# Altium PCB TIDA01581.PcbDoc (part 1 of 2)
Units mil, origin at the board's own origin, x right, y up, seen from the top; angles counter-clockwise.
Board outline 3050 x 2610 mil, 2 copper layers (Top Layer, Bottom Layer), stack 62 mil thick; 135 components, 67 nets, 345 pads, 231 vias.
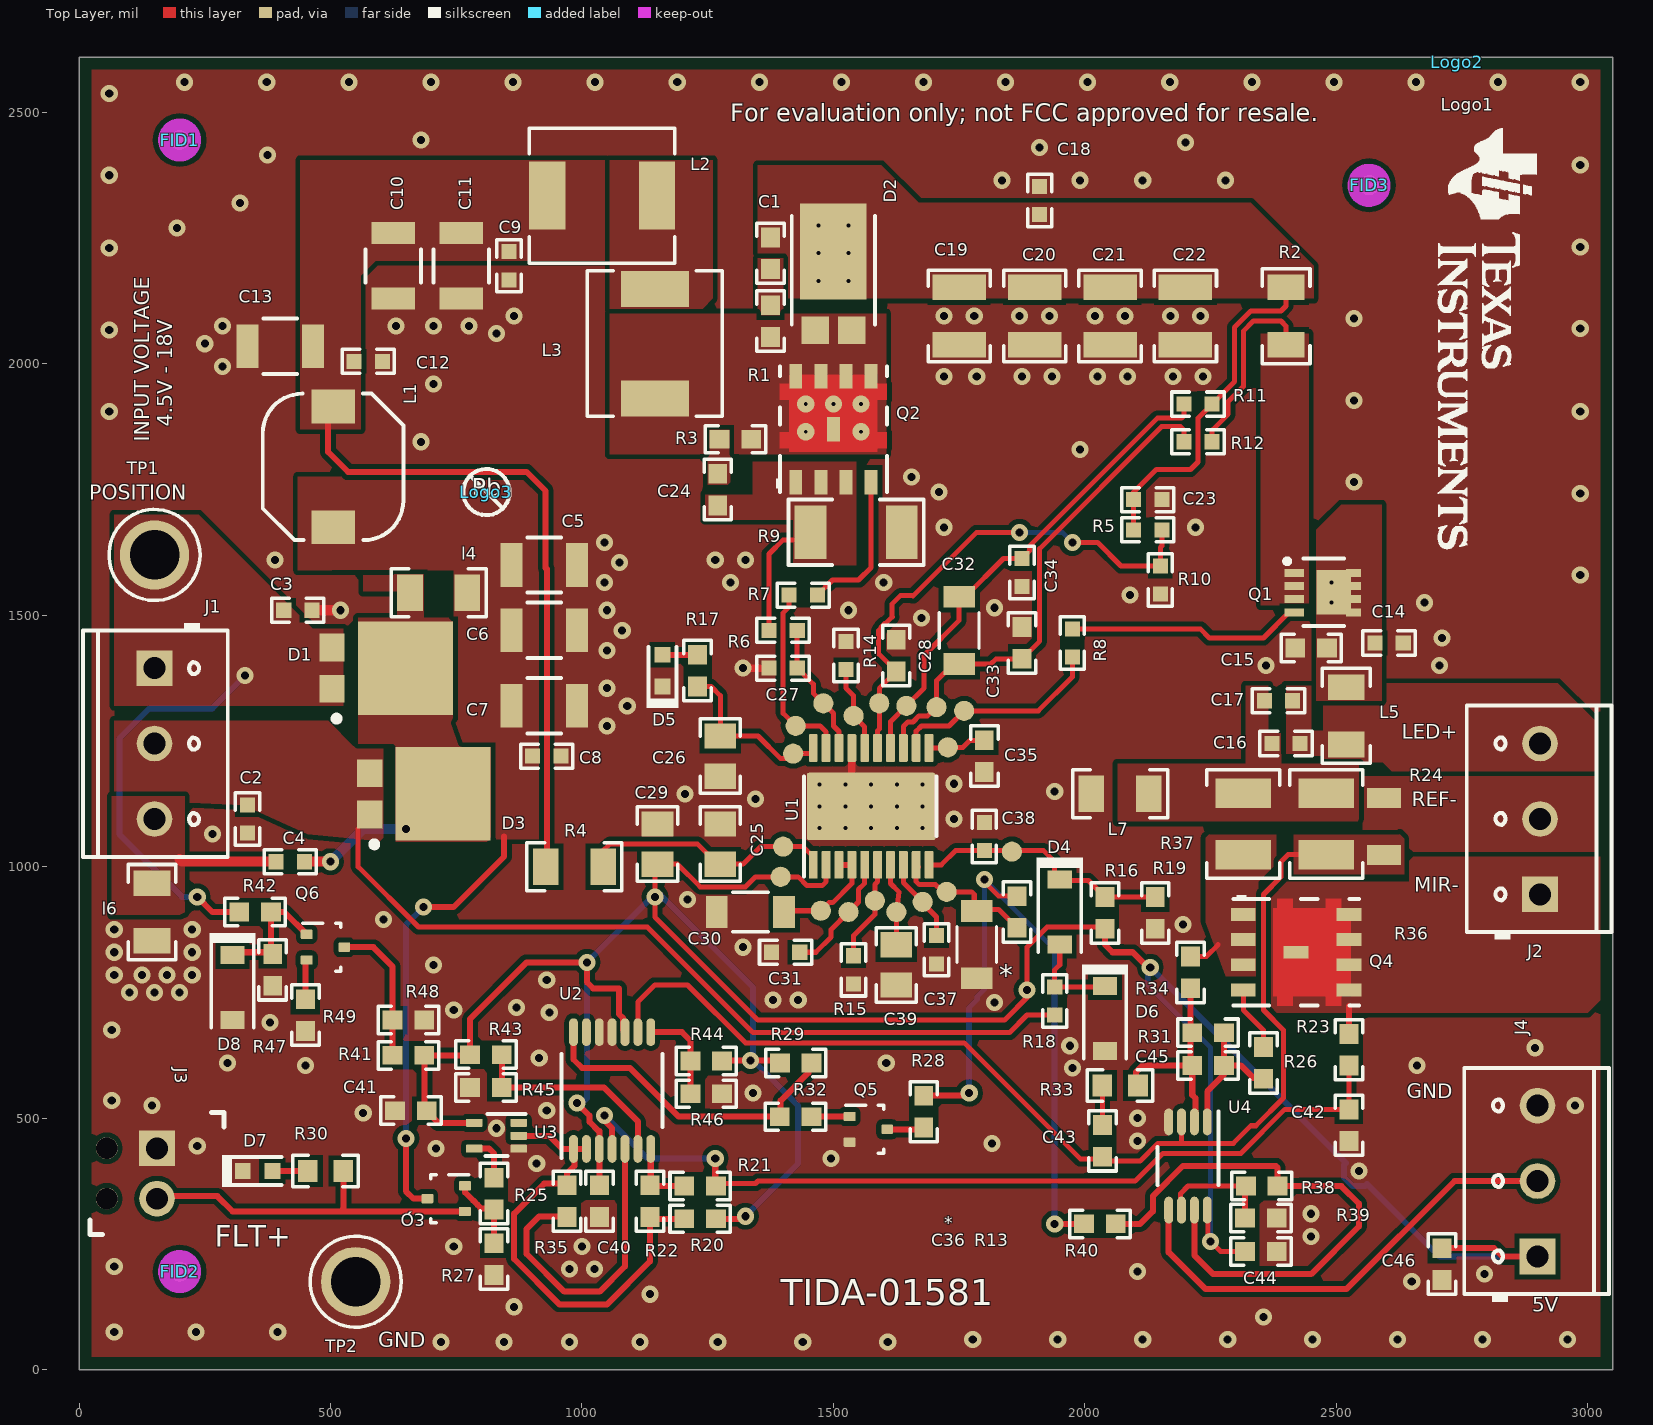
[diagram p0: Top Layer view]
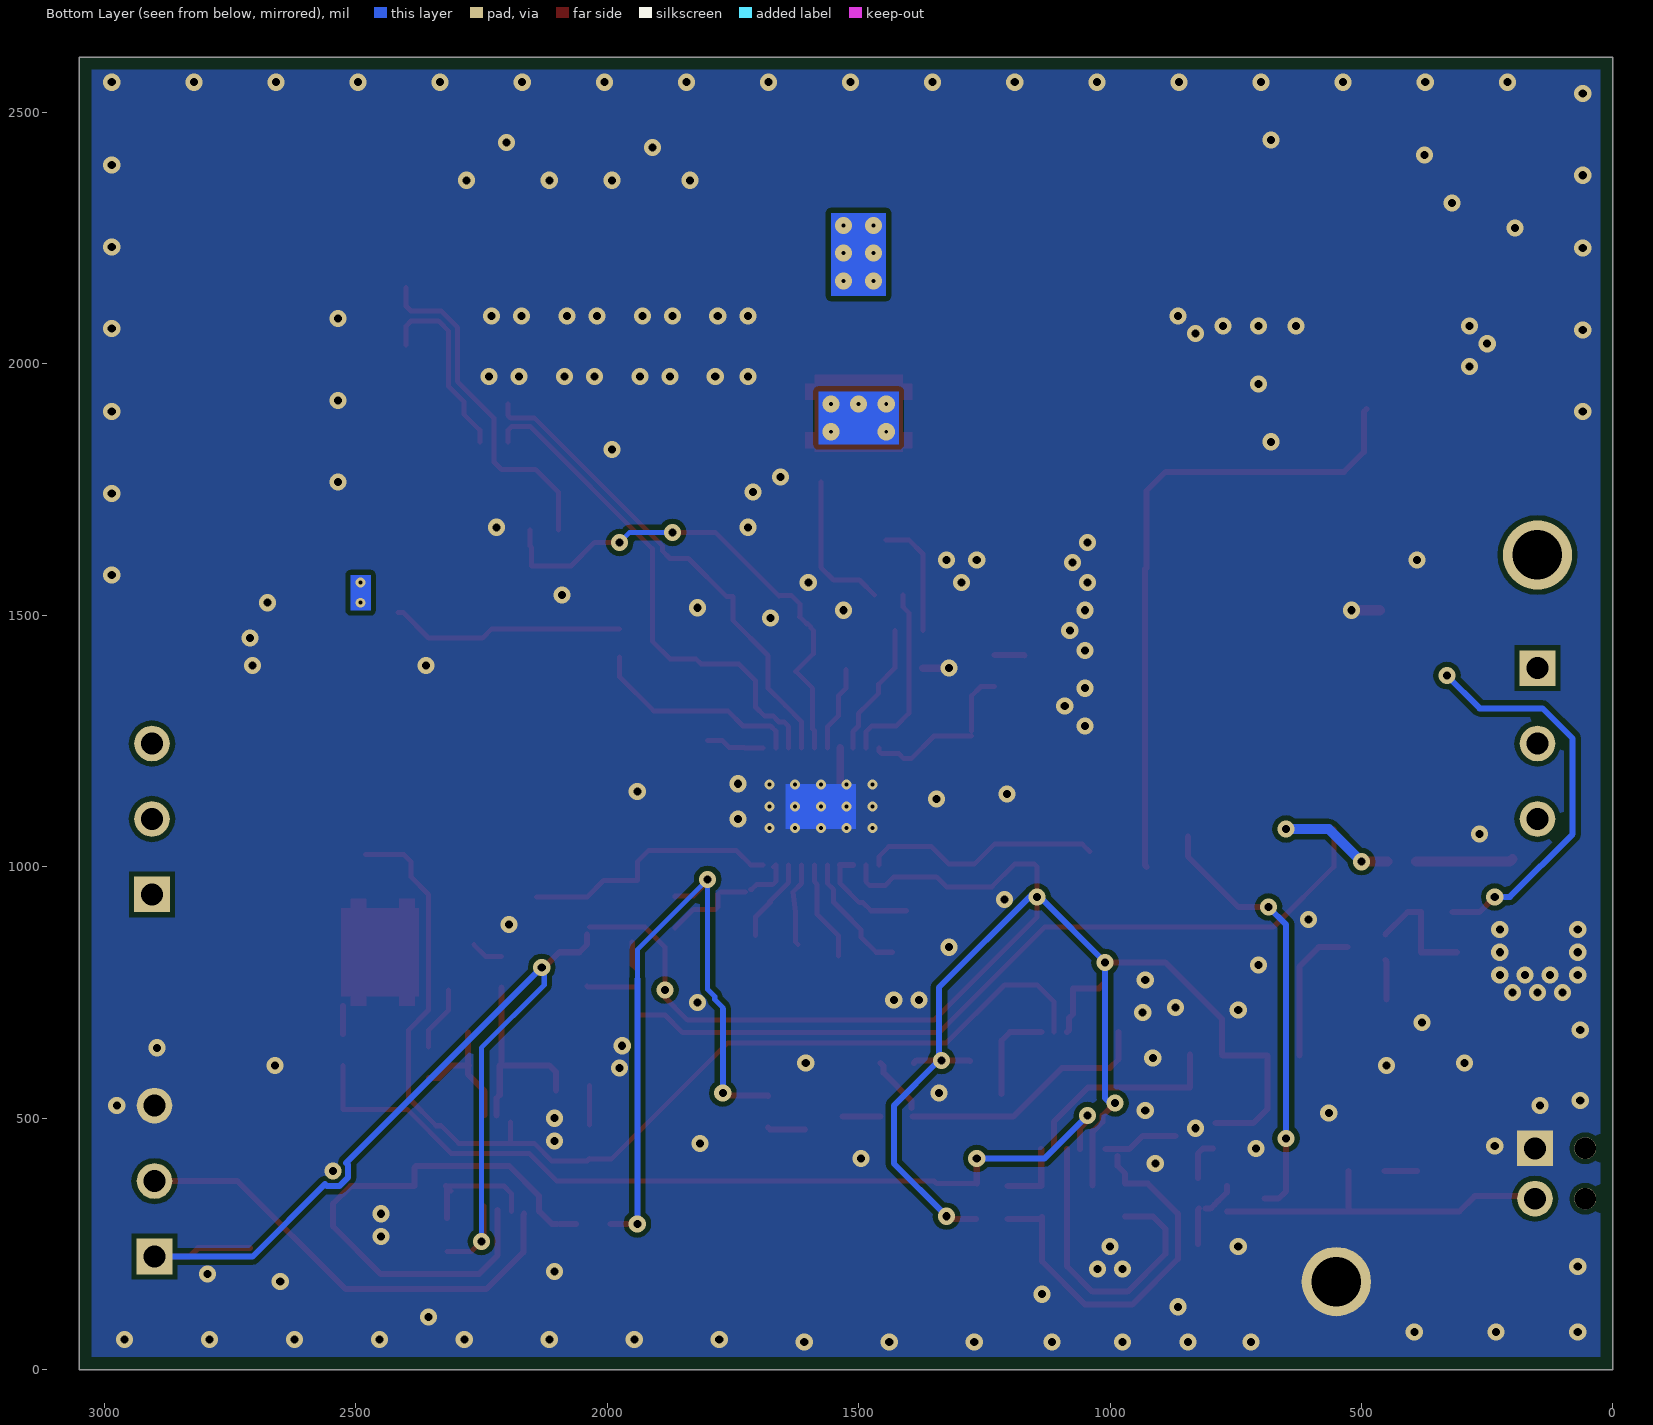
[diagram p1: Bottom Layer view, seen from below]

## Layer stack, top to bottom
Top Solder: solder mask 0.4, Solder Resist, Dk 3.5
Top Layer: signal copper 1.4
Dielectric1: core 59.2, FR-4, Dk 4.8
Bottom Layer: signal copper 1.4
Bottom Solder: solder mask 0.4, Solder Resist, Dk 3.5

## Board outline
0,0 0,2610 3050,2610 3050,0

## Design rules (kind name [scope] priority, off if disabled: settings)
AcuteAngle [All] p1: minimum=4.00000000000000E+0001 checktracksonly=FALSE
AssemblyTestPointUsage [All] p1: valid=2
BoardOutlineClearance BoardOutlineClearance_MountingHoles [OnCopper and InComponentClass('Mounting Holes')] p1: gap=40
BoardOutlineClearance BoardOutlineClearance_Poly [OnCopper and InPoly] p2: gap=25
BoardOutlineClearance [OnCopper and Not InComponentClass('Logo') and not InComponentClass('FiducialMark') and not InRegion(1000,500,4000,800)] p3: gap=25
Clearance Clearance_Keepouts [((IsTrack Or IsArc) And Not InPoly) And IsFree and IsKeepOut vs ((IsTrack Or IsArc) And Not InPoly) And IsFree and IsKeepOut] p1: gap=0
Clearance Clearance_Poly [InPolygon] p2: gap=10
Clearance [All] p3: gap=7
ComponentClearance ComponentClearance_Logo4-R11 [InComponent('LOGO4') vs InComponent('R11')] p1: gap=-1 collisioncheckmode=3 verticalgap=-1 showdistances=FALSE
ComponentClearance ComponentClearance_Logo1-SHJ4 [InComponent('Logo1') vs InComponent('SH-J4')] p2: gap=-1 collisioncheckmode=3 verticalgap=-1 showdistances=FALSE
ComponentClearance ComponentClearance_Logo1-J4 [InComponent('Logo1') vs InComponent('J4')] p3: gap=-1 collisioncheckmode=3 verticalgap=-1 showdistances=FALSE
ComponentClearance ComponentClearance_Shunts [HasFootprint('Wurth_60900213521') vs InComponentClass('Header')] p4: gap=-1 collisioncheckmode=3 verticalgap=-1 showdistances=FALSE
ComponentClearance [All] p5: gap=5 collisioncheckmode=3 verticalgap=5 showdistances=FALSE
DiffPairsRouting [All] p1: maxlimit=100 minlimit=10 mostfreqgap=10 toplayer_minwidth=15 toplayer_maxwidth=15 toplayer_prefwidth=15 bottomlayer_minwidth=15 bottomlayer_maxwidth=15 bottomlayer_prefwidth=15 maxuncoupledlength=1000
FabricationTestPointUsage TestPointUsage [All] p1: valid=2 allowmultiple=FALSE
FabricationTestpoint Testpoint [All] p1: side=3 testpointundercomponent=TRUE minsize=40 maxsize=100 preferedsize=60 minholesize=0 maxholesize=40 preferedholesize=32 testpointgrid=1 allowsidetop=TRUE allowsidebottom=TRUE usegrid=TRUE gridtolerance=0.01
FanoutControl Fanout_LCC [IsLCC] p1: bgadir=Out bgaviamode=Centered fanoutstyle=Auto fanoutdirection=Alternating viagrid=1 // Fanout_LCC (Default Rule)
FanoutControl Fanout_BGA [IsBGA] p2: bgadir=Out bgaviamode=Centered fanoutstyle=Auto fanoutdirection=Alternating viagrid=1 // Fanout_BGA (Default Rule)
FanoutControl Fanout_Default [All] p4: bgadir=Out bgaviamode=Centered fanoutstyle=Auto fanoutdirection=Alternating viagrid=1 // Fanout_Default (Default Rule)
FanoutControl Fanout_Small [(CompPinCount < 5)] p5: bgadir=Out bgaviamode=Centered fanoutstyle=Auto fanoutdirection=OutThenIn viagrid=1 // Fanout_Small (Default Rule)
HoleSize [All] p1: absolutevalues=TRUE maxlimit=251 minlimit=7.87 maxpercent=80.000 minpercent=20.000
MinimumAnnularRing MinimumAnnularRing_ThermalPadVias [IsVia and InAnyComponent] p1: minimumring=5.91
MinimumAnnularRing [All] p2: minimumring=8
MinimumSolderMaskSliver MinimumSolderMaskSliver_Logo [InComponentClass('Logo') vs InComponentClass('Logo')] p1: minsoldermaskwidth=0.7
MinimumSolderMaskSliver [All] p2: minsoldermaskwidth=3.94
PlaneConnect [All] p1: planeconnectstyle=Relief reliefexpansion=10 reliefentries=4 reliefconductorwidth=10 reliefairgap=10
PolygonConnect [All] p1: connectstyle=Direct reliefconductorwidth=10 reliefentries=4 polygonreliefangle="90 Angle" airgapwidth=10
RoutingVias ThermalPadVias [IsVia and InAnyComponent] p1: holewidth=7.87 width=19.68 viastyle="Through Hole" minholewidth=7.87 minwidth=19.68 maxholewidth=12.99 maxwidth=23.62
RoutingVias [All] p2: holewidth=16 width=34 viastyle="Through Hole" minholewidth=7.87 minwidth=26 maxholewidth=40 maxwidth=65
SilkToBoardRegionClearance [Not ((IsComment or IsDesignator) And (Hide <> 'False')) and not InRegion(1000,500,4000,800)] p1:
SilkToSilkClearance SilkToSilkClearance_Pb-FreeLogo [(HasFootprint('Pb-Free_Overlay_Medium') OR HasFootprint('Pb-Free_Overlay_Small')) vs (HasFootprint('Pb-Free_Overlay_Medium') OR HasFootprint('Pb-Free_Overlay_Small'))] p1: silktosilkclearance=0
SilkToSilkClearance [All] p2: silktosilkclearance=3
SilkToSolderMaskClearance SilkToComponentPadClearance [IsPad and InAnycomponent] p1: minsilkscreentomaskgap=4 clearancetoexposedcopper=TRUE
SilkToSolderMaskClearance "Silk to Solder Mask Opening" [All] p2: minsilkscreentomaskgap=4 clearancetoexposedcopper=FALSE
SolderMaskExpansion [All] p1: expansion=1.97
Width [All] p1: maxlimit=100 minlimit=6 preferedwidth=10 checkconnectedcopper=TRUE
15 further rules are at their usual default settings.

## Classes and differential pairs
component class TIDA01581_1: C1 C2 C3 C4 C5 C6 C7 C8 C9 C10 C11 C12 C13 C14 C15 C16 C17 C18 C19 C20 C21 C22 C23 C24 C25 C26 C27 C28 C29 C30 C31 C32 C33 C34 C35 C36 C37 C38 C39 D1 D2 D3 D4 D8 J1 L1 L2 L3 l4 L5 l6 L7 Q1 Q2 R1 R2 R3 R4 R5 R6 R7 R8 R9 R10 R11 R12 R13 R14 R15 R16 R18 R19 R20 TP1 TP2 U1
component class Logo: Logo1
component class TIDA01581_Hardware: FID1 FID2 FID3 Logo1 Logo2 Logo3 ZZ1 ZZ2 ZZ3
component class FiducialMark: FID1 FID2 FID3
component class AssemblyNote: ZZ1 ZZ2 ZZ3
component class TIDA01581_2: C40 C41 C42 C43 C44 C45 C46 D7 D8 J2 J3 J4 Q3 Q4 Q5 Q6 R21 R22 R23 R24 R25 R26 R28 R29 R31 R32 R33 R34 R35 R36 R37 R38 R39 R40 R41 R42 R43 R44 R45 R46 R47 R48 R49 U2 U3 U4

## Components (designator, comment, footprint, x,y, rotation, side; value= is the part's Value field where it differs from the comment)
C1 "06031C103MAT2A" 0603 1375,2220 r90 top
C2 "CGA3E2X7R2A472K080AA" 0603_HV 335,1095 r270 top
C3 "CGA3E2X7R2A472K080AA" 0603_HV 435,1510 r0 top
C4 "CGA3E2X7R1H104K080AA" 0603_HV 420,1010 r180 top
C5 "CGA6P3X7S1H106K250AB" 1210_280 925,1600 r0 top
C6 "CGA6P3X7S1H106K250AB" 1210_280 925,1470 r0 top
C7 "CGA6P3X7S1H106K250AB" 1210_280 925,1320 r0 top
C8 "CGA3E2X7R1H104K080AA" 0603_HV 930,1220 r0 top
C9 "CGA3E2X7R1H104K080AA" 0603_HV 855,2195 r270 top
C10 "CGA6P3X7S1H106K250AB" 1210_280 625,2195 r270 top
C11 "CGA6P3X7S1H106K250AB" 1210_280 760,2195 r270 top
C12 "CGA3E2X7R1H104K080AA" 0603_HV 575,2005 r0 top
C13 "CGA6P3X7S1H106K250AB" 1210_280 400,2035 r180 top
C14 "CGA3E2X7R1H104K080AA" 0603_HV 2605,1445 r0 top
C15 "CGA3E2X7R2A103K080AA" 0603 2450,1435 r180 top
C16 "CGA3E2X7R2A103K080AA" 0603_HV 2400,1245 r0 top
C17 "CGA3E2X7R1H104K080AA" 0603_HV 2385,1330 r180 top
C18 "CGA3E2X7R1H104K080AA" 0603_HV 1910,2325 r90 top
C19 "CGA6M3X7S2A475K200AB" 1210_220 1750,2095 r90 top
C20 "CGA6M3X7S2A475K200AB" 1210_220 1900,2095 r90 top
C21 "CGA6M3X7S2A475K200AB" 1210_220 2050,2095 r90 top
C22 "CGA6M3X7S2A475K200AB" 1210_220 2200,2095 r90 top
C23 "CGA3E2X7R1H104K080AA" 0603_HV 2125,1730 r0 top
C24 "06031C103MAT2A" 0603 1270,1750 r270 top
C25 "C2012X7R2A104K125AA" 0805_HV 1275,1045 r270 top
C26 "CGA4J3X7R1E225K125AB" 0805_HV 1275,1220 r270 top
C27 "CGA3E2X7R2A102K080AA" 0603_HV 1400,1395 r180 top
C28 "CGA3E2X7R2A102K080AA" 0603 1625,1420 r90 top
C29 "CGA4J3X7R1E225K125AB" 0805_HV 1150,1045 r270 top
C30 "CGA5L2X7R2A104K160AA" 1206_180 1335,910 r0 top
C31 "CGA3E2X7R2A223K080AA" 0603_HV 1405,830 r0 top
C32 "CGA5L2X7R2A104K160AA" 1206_180 1750,1470 r270 top
C33 "CGA3E2X7R2A103K080AA" 0603 1875,1445 r90 top
C34 "CGA3E2X7R2A103K080AA" 0603_HV 1875,1585 r270 top
C35 "CGA3E2X7R2A103K080AA" 0603 1800,1220 r270 top
C36 "CGA5L2X7R2A104K160AA" 1206_180 1785,845 r270 top
C37 "CGA3E2C0G1H100D080AA" 0603_HV 1705,835 r270 top
C38 "CGA3E2X7R2A103K080AA" 0603_HV 1800,1060 r90 top
C39 "CEU4J2X7R1H104K125AE" 0805_HV 1625,805 r90 top
C40 "0603ZC104KAT2A" 0603 1035,335 r270 top
C41 "0603ZC104KAT2A" 0603 660,515 r180 top
C42 "C0603C225K8PACTU" 0603 2525,486.02 r270 top
C43 "06031C332JAT2A" 0603 2035,455 r90 top
C44 "0603ZC104KAT2A" 0603 2350,235 r0 top
C45 "0603ZC104KAT2A" 0603 2245,605 r180 top
C46 "0603ZC104KAT2A" 0603 2710,210 r270 top
D1 "V12P10-M3/86A" TO-277A 575,1395 r90 top
D2 "PDS3100Q-13" PowerDI5 1500,2145 r90 top
D3 "V12P10-M3/86A" TO-277A 650,1145 r90 top
D4 "BAT42W-7-F" SOD-123 1950,910 r270 top
D5 "150060VS75000" WL-SMCW_GREEN 1160,1390 r90 top
D6 "MMSZ5240B-7-F" SOD-123 2040,698.05 r270 top
D7 "19-21SURC/S530-A3/TR8" 19-21_Red 355,395 r0 top
D8 "BZT52C16-7-F" SOD-123 305,760 r270 top
FID1 "Fiducial" Fiducial10-20 200,2445 r0 top
FID2 "Fiducial" Fiducial10-20 200,195 r0 top
FID3 "Fiducial" Fiducial10-20 2565,2355 r0 top
J1 "1727023" Phoenix_1727023 150,1245 r270 top
J2 "1727023" Phoenix_1727023 2905,1095 r90 top
J3 "1725656" CONN_1725656 155,390 r270 top
J4 "1727023" Phoenix_1727023 2900,375 r90 top
L1 "CLF7045T-3R3N" CLF7045 505,1795 r90 top
L2 "IHLP2525BDER100M01" IHLP-2525BD 1040,2335 r0 top
L3 "IHLP2525BDER100M01" IHLP-2525BD 1145,2040 r270 top
l4 "FBMH3216HM221NTV" 1206 715,1545 r0 top (schematic designator L4)
L5 "MI1206K601R-10" 1206 2520,1300 r270 top
l6 "FBMH3216HM221NTV" 1206 145,910 r270 top (schematic designator L6)
L7 "MI1206K601R-10" 1206 2070,1145 r0 top
Logo1 "Texas Instruments" TI_Stacked_Overlay_Small 2800,2050 r270 top
Logo2 "FCC disclaimer" FCC_disclaimer 2740,2600 r0 top
Logo3 "Pb-Free Symbol" Pb-Free_Overlay_Small 810,1745 r0 top
Q1 "SI7415DN-T1-GE3" PowerPAK_1212-8 2475,1545 r0 top
Q2 "STL8N10LF3" PowerFLAT5x6_R 1500,1870 r90 top
Q3 "BSS138PW,115" SOT-323#1 730,340 r180 top
Q4 "STL8N10LF3" PowerFLAT5x6_R 2420,830 r0 top
Q5 "BSS138PW,115" SOT-323#2 1569.64,477.97 r0 top
Q6 "BSS138PW,115" SOT-323#2 490,840 r0 top
R1 "CRCW060350R0FKEA" 0603 1375,2085 r270 top
R2 "CSR1206FKR330" 1206 2400,2095 r270 top
R3 "CRCW060350R0FKEA" 0603 1305,1850 r0 top
R4 "CRCW120610R0FKEA" 1206 985,1000 r180 top
R5 "CRCW0603150KFKEA" 0603_HV 2125,1670 r180 top
R6 "CRCW0603100RFKEA" 0603_HV 1400,1470 r180 top
R7 "CRCW06030000Z0EA" 0603_HV 1440,1540 r180 top
R8 "CRCW06030000Z0EA" 0603_HV 1975,1445 r270 top
R9 "CSRN2010FK60L0" 2010 1545,1665 r180 top
R10 "CRCW06033K01FKEA" 0603_HV 2150,1570 r90 top
R11 "CRCW060310R0FKEA" 0603_HV 2225,1920 r0 top
R12 "CRCW060310R0FKEA" 0603_HV 2225,1845 r0 top
R13 "CRCW06031K00JNEA" 0603 1865,910 r270 top
R14 "CRCW0603105KFKEA" 0603_HV 1525,1420 r270 top
R15 "CRCW060320K0FKEA" 0603_HV 1540,795 r270 top
R16 "CRCW060333K0FKEA" 0603 2040,908.05 r90 top
R17 "CRCW06031K00JNEA" 0603 1230,1390 r90 top
R18 "CRCW060310K0FKEA" 0603_HV 1940,733.05 r270 top
R19 "CRCW060310K0FKEA" 0603 2140,908.05 r90 top
R20 "CRCW06035K10JNEA" 0603 1235,300 r0 top
R21 "CRCW060320K0JNEA" 0603 1235,365 r180 top
R22 "CRCW0603732KFKEA" 0603 1135,335 r270 top
R23 "CRCW060347K0JNEA" 0603 2525,636.02 r270 top
R24 "5108" 5108 2595,1080 r90 top
R25 "CRCW060310K0JNEA" 0603 825,350 r270 top
R26 "CRCW060350R0FKEA" 0603 2355,610 r90 top
R27 "CRCW0603100KFKEA" 0603 825,220 r90 top
R28 "CRCW0603110RJNEA" 0603 1679.64,512.97 r270 top
R29 "CRCW06035K10JNEA" 0603 1425,610 r180 top
R30 "CPF0603B2K0E" CPF0603 490,395 r0 top
R31 "CRCW06031M00FKEA" 0603 2245,670 r0 top
R32 "CRCW060350R0FKEA" 0603 1424.64,502.97 r180 top
R33 "CPF0603B2K0E" CPF0603 2070,565 r180 top
R34 "CRCW060347K0FKEA" 0603 2210,790 r90 top
R35 "CRCW0603390KJNEA" 0603 970,335 r90 top
R36 "ERJ-14BQF2R0U" 1210M 2480,1085 r270 top
R37 "ERJ-14BQF2R0U" 1210M 2315,1085 r270 top
R38 "CRCW060312K1FKEA" 0603 2351.81,365.02 r0 top
R39 "CRCW060340K2FKEA" 0603 2350,301.32 r180 top
R40 "CRCW060310K0JNEA" 0603 2030,290 r180 top
R41 "CRCW06034K99FKEA" 0603 655,625 r0 top
R42 "CRCW060320K0JNEA" 0603 350,910 r180 top
R43 "CRCW0603100KFKEA" 0603 809.06,626.3 r180 top
R44 "CRCW0603100KFKEA" 0603 1247.01,613.54 r0 top
R45 "CRCW060325K5FKEA" 0603 809.06,561.3 r0 top
R46 "CRCW06037K15FKEA" 0603 1247.01,548.54 r180 top
R47 "CRCW0603100KFKEA" 0603 385,795 r90 top
R48 "CRCW0603200KFKEA" 0603 655,695 r180 top
R49 "CRCW060315K0FKEA" 0603 450,705 r90 top
TP1 "POSITION" Keystone1502-2 150,1620 r0 top
TP2 "GND" Keystone1502-2 550,175 r0 top
U1 "TPS92692QPWPRQ1" PWP0020D_N 1575,1120 r90 top locked
U2 "LM2901VQPWRQ1" PW0014A_N 1060,555 r90 top
U3 "CAHCT1G04QDCKRQ1" DCK0005A_N 830,465 r180 top
U4 "TLV2316QDGKRQ1" DGK0008A_N 2205,405 r270 top
ZZ1 "These assemblies are ESD sensitive, ESD precautions shall be observed." AssemblyNote 185,3824.11 r0 top
ZZ2 "These assemblies must be clean and free from flux and all contaminants. Use of no clean flux is not acceptable." AssemblyNote 185,3735.56 r0 top
ZZ3 "These assemblies must comply with workmanship standards IPC-A-610 Class 2, unless otherwise specified." AssemblyNote 185,3647 r0 top

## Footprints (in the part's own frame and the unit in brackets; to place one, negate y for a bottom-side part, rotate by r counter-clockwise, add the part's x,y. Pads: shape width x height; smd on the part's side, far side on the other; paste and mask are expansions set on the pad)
19-21_Red [mm] "SMD, 2-Leads, Body 0.8x1.6mm, Pin Spacing 1.5mm"
  rect 0.8x0.8 smd: 1(-0.75,0) 2(0.75,0)
  silkscreen extent -1.8,-0.8 1.2,0.8, body extent -0.9,-0.45 0.9,0.45, height 1.01
0603 [mm] "0603 from SM-752 data"
  rect 1x0.95 smd: 1(-0.8,0) 2(0.8,0)
  silkscreen extent -1.52,-0.69 1.52,0.69, body extent -0.87,-0.47 0.87,0.47, height 1
0603_HV [mil] "Ernesto recommended land pattern.  26 mil between pads."
  rect 30x30 smd: 1(-28,0) 2(28,0)
  silkscreen extent -52,-24 52,24, body extent -34,-19 34,19, height 39
0805_HV [mil] "0805 with 30mil clearance between pads"
  rect 50x63 smd: 1(-40,0) 2(40,0)
  silkscreen extent -74,-40 74,40, body extent -43,-29 43,29, height 57
1206 [mm] "1206 from SM-752 data"
  rect 1.3x1.85 smd: 1(-1.45,0) 2(1.45,0)
  silkscreen extent -2.4,-1.21 2.4,1.21, body extent -1.7,-0.9 1.7,0.9, height 1.35
1206_180 [mm] "1206_180"
  rect 1.1x1.6 smd: 1(-1.7,0) 2(1.7,0)
  silkscreen extent -0.9,-1 0.9,1, body extent -1.75,-0.95 1.75,0.95, height 1.8
1210_220 [mm] "1210"
  rect 1.3x2.7 smd: 1(-1.45,0) 2(1.45,0)
  silkscreen extent -2.32,-1.57 2.32,1.57, body extent -1.7,-1.35 1.7,1.35, height 2.2
1210_280 [mm] "SMD, 2-Leads, Body 3.6x2.8mm, Height 2.8mm"
  rect 1.1x2.2 smd: 1(-1.65,0) 2(1.65,0)
  silkscreen extent -0.84,-1.4 0.84,1.4, body extent -1.8,-1.4 1.8,1.4, height 2.8
1210M [mm] "1210 from SM-752 data"
  rect 1.5x2.8 smd: 1(-1.55,0) 2(1.55,0)
  silkscreen extent -2.75,-1.85 2.75,1.85, body extent -1.7,-1.35 1.7,1.35, height 1.35
2010 [mm] "Chip Capacitor, Body 5.08x2.54mm, IPC Medium Density"
  rect 1.6x2.7 smd: 1(-2.3,0) 2(2.3,0)
  silkscreen extent -3.42,-1.65 3.42,1.65, body extent -2.73,-1.45 2.73,1.45, height 1.66
5108 [mm] "Keystone"
  rect 1.01x1.73 smd: 1(-1.445,0) 2(1.445,0)
  body extent -1.52,-0.85 1.52,0.85, height 0.71
AssemblyNote [mil] "Assembly Note"
CLF7045 [mm] "TDK"
  rect 1.7x2.2 smd: 1(-3.05,0) 2(3.05,0)
  silkscreen extent -3.7,-3.55 3.7,3.55, body extent -3.7,-3.55 3.7,3.55, height 4.8
CONN_1725656 [mm] "Phoenix Contact"
  rect 1.8x1.8 hole 1.1: 1(-1.27,0)
  round 1.8 hole 1.1: 2(1.27,0)
  round 1.1 hole 1.1 unplated: MH1(-1.275,-2.54) MH2(1.27,-2.54)
  silkscreen extent -3.08,-3.37 3.08,3.37, body extent -2.77,-3.1 2.77,3.1, height 8.52
CPF0603 [mm] "TE Connectivity"
  rect 1x1.1 smd: 1(-0.9,0) 2(0.9,0)
  silkscreen extent -1.65,-0.8 1.65,0.8, body extent -0.82,-0.45 0.82,0.45, height 0.55
DCK0005A_N [mm] "SOT353, 5-Leads, Body 2x1.3mm, Pitch 0.65mm, Lead Span 2.1mm, IPC Medium Density"
  rrect25% 0.85x0.4 smd: 1(-1.125,-0.65) 2(-1.125,0) 3(-1.125,0.65) 4(1.125,0.65) 5(1.125,-0.65)
  silkscreen extent -1.48,-1.1 0.55,1.02, body extent -1.14,-1 1.14,1, height 1.09
DGK0008A_N [mm] "TSOP, 8-Leads, Body 3x3mm, Pitch 0.65mm, IPC Medium Density"
  oval 1.35x0.45 smd: 1(-2.225,0.975) 2(-2.225,0.325) 3(-2.225,-0.325) 4(-2.225,-0.975) 5(2.225,-0.975) 6(2.225,-0.325) 7(2.225,0.325) 8(2.225,0.975)
  silkscreen extent -2.75,-1.55 0.95,1.55, body extent -2.45,-1.5 2.45,1.5, height 1.24
FCC_disclaimer [mil]
Fiducial10-20 [mm]
  round 1 smd mask+0.5: 1(0,0)
  Top Layer keep-out circle w1.178: c0,0 r0.5
IHLP-2525BD [mm] "Vishay Dale recommended land pattern.  Document 34190 rev 10-Aug-06"
  rect 1.83x3.43 smd: 1(-2.77,0) 2(2.77,0)
  silkscreen extent -3.67,-3.42 3.67,3.4, body extent -3.62,-3.36 3.62,3.36, height 2.4
Keystone1502-2 [mm] "Double Turret"
  round 3.5 hole 2.5: 1(0,0)
  silkscreen extent -2.3,-2.3 2.3,2.3, body extent -1.6,-1.6 1.59,1.6, height 5.62
Pb-Free_Overlay_Small [mil]
  silkscreen extent -46,-46 46,46
Phoenix_1727023 [mm] "Phoenix Contact"
  rect 1.8x1.8 hole 1.1: 1(-3.81,0)
  round 1.8 hole 1.1: 2(0,0) 3(3.81,0)
  silkscreen extent -6.1,-3.6 5.72,3.7, body extent -5.71,-3.6 5.72,3.7, height 8.5
PowerDI5 [mm] "Diodes Inc recommended land pattern, ap02001.pdf rev 60"
  rect 1.4x1.39 smd: 1(-1.991,0.92) 2(-1.991,-0.92)
  rect 4.86x3.36 smd: 3(1.991,0)
  silkscreen extent -1.7,-2.1 3.8,2.1, body extent -2.27,-2.03 4.33,2.03, height 1.17
PowerFLAT5x6_R [mm] "SMD, 8-Leads, Body 6.15x5.2mm, Pitch 1.27mm"
  rect 1.25x0.65 smd: 1(-2.675,1.905) 2(-2.675,0.635) 3(-2.675,-0.635) 4(-2.675,-1.905) 5(2.675,-1.905) 6(2.675,-0.635) 7(2.675,0.635) 8(2.675,1.905) 9(0,0)
  Top Layer region: -0.96,2.7 -0.96,2.225 -1.15,2.225 -1.15,-2.225 -0.96,-2.225 -0.96,-2.7 -0.16,-2.7 -0.16,-2.225 1.49,-2.225 1.49,-2.7 2.29,-2.7 2.29,-2.225 2.75,-2.225 2.75,2.225 2.29,2.225 2.29,2.7 1.49,2.7 1.49,2.225 -0.16,2.225 -0.16,2.7
  silkscreen extent -3.17,-2.7 3.17,2.9, body extent -3.17,-2.7 3.17,2.7, height 1.01
PowerPAK_1212-8 [mil] "Vishay PowerPAK 1212-8, Body 3.4x3.2mm (max), Pitch 0.65mm, IPC Medium Density"
  rect 39x16 smd mask+2.01: 1(-58.75,39) 2(-58.75,13) 3(-58.75,-13) 4(-58.75,-39)
  rect 30x16 smd mask+2.01: 5(58.75,-39) 6(58.75,-13) 7(58.75,13) 8(58.75,39)
  rect 68x88 smd mask+2.01: 9(19.75,0.61)
  silkscreen extent -78,-66 40,68, body extent -65,-65 65,65, height 43
PW0014A_N [mm] "TSOP, 14-Leads, Body 5x4.4mm, Pitch 0.65mm, IPC Medium Density"
  oval 1.4x0.45 smd: 1(-2.95,1.95) 2(-2.95,1.3) 3(-2.95,0.65) 4(-2.95,0) 5(-2.95,-0.65) 6(-2.95,-1.3) 7(-2.95,-1.95) 8(2.95,-1.95) 9(2.95,-1.3) 10(2.95,-0.65) 11(2.95,0) 12(2.95,0.65) 13(2.95,1.3) 14(2.95,1.95)
  silkscreen extent -3.4,-2.55 1.85,2.55, body extent -3.21,-2.5 3.21,2.5, height 1
PWP0020D_N [mm] "SOP, 20-Leads, Body 6.4x4.4mm, Pitch 0.65mm, Thermal Pad 2x3mm, IPC Medium Density"
  rrect22% 1.4x0.45 smd: 1(-2.95,2.925) 2(-2.95,2.275) 3(-2.95,1.625) 4(-2.95,0.975) 5(-2.95,0.325) 6(-2.95,-0.325) 7(-2.95,-0.975) 8(-2.95,-1.625) 9(-2.95,-2.275) 10(-2.95,-2.925) 11(2.95,-2.925) 12(2.95,-2.275) 13(2.95,-1.625) 14(2.95,-0.975) 15(2.95,-0.325) 16(2.95,0.325) 17(2.95,0.975) 18(2.95,1.625) 19(2.95,2.275) 20(2.95,2.925)
  rrect6% 3.4x6.5 smd paste-2 mask-2: 21(0,0)
  rrect4% 2.4x3.7 on Top Paste: 21(0,0)
  rrect4% 2.4x3.7 on Top Solder: 21(0,0)
  silkscreen extent -3.55,-3.3 1.5,3.4, body extent -3.21,-3.25 3.21,3.25, height 1
SOD-123 [mm] "On Semi recommended land pattern"
  rect 0.915x1.22 smd: 1(-1.637,0) 2(1.637,0)
  silkscreen extent -2.74,-1.17 2.03,1.17, body extent -1.93,-0.9 1.93,0.9, height 1.35
SOT-323#1 [mm] "Diodes Inc recommended land pattern.  2016-02-24"
  rrect21% 0.6x0.47 smd: 1(-0.95,-0.65) 2(-0.95,0.65) 3(0.95,0)
  silkscreen extent -1.14,-1.22 0.77,1.22, body extent -1.13,-1.12 1.12,1.13, height 1.13
SOT-323#2 [mm] "Diodes Inc recommended land pattern.  2016-02-24"
  rrect21% 0.6x0.47 smd: 1(-0.95,0.65) 2(-0.95,-0.65) 3(0.95,0)
  silkscreen extent -1.14,-1.22 0.77,1.22, body extent -1.13,-1.13 1.12,1.12, height 1.13
TI_Stacked_Overlay_Small [mil]
  silkscreen extent -418,-98 418,98
TO-277A [mm] "Vishay"
  rect 1.4x1.27 smd: 1(-1.04,1.83) 2(1.04,1.83)
  rect 4.72x4.8 smd: 3(0,-1.883)
  silkscreen extent -2.7,1.45 -2.4,1.75, body extent -2.35,-4.2 2.4,2.45, height 1.2
WL-SMCW_GREEN [mm] "WURTH"
  rect 0.8x0.8 smd: 1(-0.8,0) 2(0.8,0)
  silkscreen extent -1.9,-0.8 1.2,0.8, body extent -0.85,-0.45 0.85,0.45, height 0.8

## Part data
C1 C24: "CAP, CERM, 0.01 µF, 100 V, +/- 20%, X7R, 0603"
C2 C3: "CAP, CERM, 4700 pF, 100 V, +/- 10%, X7R, AEC-Q200 Grade 1, 0603"
C4 C8 C9 C12 C14 C17 C18 C23: "CAP, CERM, 0.1 µF, 50 V, +/- 10%, X7R, AEC-Q200 Grade 1, 0603"
C5 C6 C7 C10 C11 C13: "CAP, CERM, 10 µF, 50 V, +/- 10%, X7S, AEC-Q200 Grade 1, 1210"
C15 C16 C33 C34 C35 C38: "CAP, CERM, 0.01 µF, 100 V, +/- 10%, X7R, AEC-Q200 Grade 1, 0603"
C19 C20 C21 C22: "CAP, CERM, 4.7 µF, 100 V, +/- 10%, X7S, AEC-Q200 Grade 1, 1210"
C25: "CAP, CERM, 0.1 µF, 100 V, +/- 10%, X7R, 0805"
C26 C29: "CAP, CERM, 2.2 µF, 25 V, +/- 10%, X7R, AEC-Q200 Grade 1, 0805"
C27 C28: "CAP, CERM, 1000 pF, 100 V, +/- 10%, X7R, AEC-Q200 Grade 1, 0603"
C30 C32 C36: "CAP, CERM, 0.1 µF, 100 V, +/- 10%, X7R, AEC-Q200 Grade 1, 1206"
C31: "CAP, CERM, 0.022 µF, 100 V, +/- 10%, X7R, AEC-Q200 Grade 1, 0603"
C37: "CAP, CERM, 10 pF, 50 V, +/- 5%, C0G/NP0, AEC-Q200 Grade 1, 0603"
C39: "CAP, CERM, 0.1 µF, 50 V, +/- 10%, X7R, AEC-Q200 Grade 1, 0805"
C40 C41 C44 C45 C46: "CAP, CERM, 0.1 µF, 10 V, +/- 10%, X7R, 0603"
C42: "CAP, CERM, 2.2 µF, 10 V, +/- 10%, X5R, 0603"
C43: "CAP, CERM, 3300 pF, 100 V, +/- 5%, X7R, 0603"
D1 D3: "Diode, Schottky, 100 V, 12 A, AEC-Q101, TO-277A"
D2: "Diode, Schottky, 100 V, 3 A, AEC-Q101, PowerDI5"
D4: "Diode, Schottky, 30 V, 0.2 A, SOD-123"
D5: "LED, Green, SMD"
D6: "Diode, Zener, 10 V, 500 mW, SOD-123"
D7: "LED, Red, SMD"
D8: "Diode, Zener, 16 V, 500 mW, AEC-Q101, SOD-123"
FID1 FID2 FID3: "Fiducial mark.  There is nothing to buy or mount."
J1 J2 J4: "Terminal Block Receptacle, 3x1, 3.81mm, R/A, TH"
J3: "Terminal Block, 100mil, 2x1, 6A, 63V, TH"
L1: "Inductor, Shielded, Ferrite, 3.3 µH, 5 A, 0.0213 ohm, SMD"
L2 L3: "Inductor, Shielded, Powdered Iron, 10 µH, 2.5 A, 0.129 ohm, SMD"
l4 l6: "Ferrite Bead, 220 ohm @ 100 MHz, 4 A, 1206"
L5 L7: "Ferrite Bead, 600 ohm @ 100 MHz, 1.5 A, 1206"
Logo1: library part TI_Logo, "Texas Instrument Corporate Signature"
Logo2: library part FCC_disclaimer, "FCC_disclaimer"
Logo3: library part Pb-Free
Q1: "MOSFET, P-CH, -60 V, -3.6 A, PowerPAK 1212"
Q2 Q4: "MOSFET, N-CH, 100 V, 20 A, AEC-Q101, 8-PowerVDFN"
Q3 Q5 Q6: "MOSFET, N-CH, 60 V, 0.32 A, AEC-Q101, SOT-323"
R1 R3 R26 R32: "RES, 50, 1%, 0.1 W, 0603"
R2: "RES, 0.33, 1%, 0.5 W, 1206"
R4: "RES, 10.0, 1%, 0.25 W, 1206"
R5: "RES, 150 k, 1%, 0.1 W, 0603"
R6: "RES, 100, 1%, 0.1 W, 0603"
R7 R8: "RES, 0, 5%, 0.1 W, 0603"
R9: "RES, 0.06, 1%, 1 W, 2010"
R10: "RES, 3.01 k, 1%, 0.1 W, 0603"
R11 R12: "RES, 10.0, 1%, 0.1 W, 0603"
R13 R17: "RES, 1.0 k, 5%, 0.1 W, 0603"
R14: "RES, 105 k, 1%, 0.1 W, 0603"
R15: "RES, 20.0 k, 1%, 0.1 W, 0603"
R16: "RES, 33.0 k, 1%, 0.1 W, 0603"
R18 R19: "RES, 10.0 k, 1%, 0.1 W, 0603"
R20 R29: "RES, 5.1 k, 5%, 0.1 W, 0603"
R21 R42: "RES, 20 k, 5%, 0.1 W, 0603"
R22: "RES, 732 k, 1%, 0.1 W, 0603"
R23: "RES, 47 k, 5%, 0.1 W, 0603"
R24: "RES, 0, 1%, 0.5 W, 1206"
R25 R40: "RES, 10 k, 5%, 0.1 W, 0603"
R27 R43 R44 R47: "RES, 100 k, 1%, 0.1 W, 0603"
R28: "RES, 110, 5%, 0.1 W, 0603"
R30 R33: "RES, 2.00 k, 0.1%, 0.063 W, 0603"
R31: "RES, 1.00 M, 1%, 0.1 W, 0603"
R34: "RES, 47.0 k, 1%, 0.1 W, AEC-Q200 Grade 0, 0603"
R35: "RES, 390 k, 5%, 0.1 W, 0603"
R36 R37: "RES, 2.00, 1%, 0.5 W, AEC-Q200 Grade 0, 1210"
R38: "RES, 12.1 k, 1%, 0.1 W, 0603"
R39: "RES, 40.2 k, 1%, 0.1 W, 0603"
R41: "RES, 4.99 k, 1%, 0.1 W, 0603"
R45: "RES, 25.5 k, 1%, 0.1 W, 0603"
R46: "RES, 7.15 k, 1%, 0.1 W, 0603"
R48: "RES, 200 k, 1%, 0.1 W, 0603"
R49: "RES, 15.0 k, 1%, 0.1 W, 0603"
TP1 TP2: library part 1502-2, "Terminal, Turret, TH, Double"
U1: "LED Controller With Spread Spectrum Frequency Modulation and Internal PWM Generator, PWP0020D (TSSOP-20)"
U2: "Automotive Quad Comparator, PW0014A"
U3: "Single Inverter Gate, DCK0005A (SOT-SC70-5)"
U4: "10-MHz, Rail-to-Rail Input/Output, Low-Voltage, 1.8-V CMOS Operational Amplifier, DGK0008A (VSSOP-8)"
ZZ1 ZZ2 ZZ3: library part AssemblyNote

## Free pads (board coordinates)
  round 40 smd: 1(1395,980) 1(1400,1040) 1(1420,1225) 1(1425,1280) 1(1475,912.5) 1(1480,1325) 1(1530,910) 1(1540,1300) 1(1582.5,932.5) 1(1591.15,1325) 1(1625,910) 1(1645,1320) 1(1677.5,930) 1(1705,1317.5) 1(1725,950) 1(1727.5,1237.5) 1(1760,1310) 1(1855,1030)

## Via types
v1: diameter 34, hole 16, Top Layer to Bottom Layer, 203 vias
v2: diameter 34, hole 7.87, Top Layer to Bottom Layer, 11 vias
v3: diameter 19.68, hole 7.87, Top Layer to Bottom Layer, 11 vias
v4: diameter 19.68, hole 7.87, Top Layer to Bottom Layer, tented both sides, 6 vias

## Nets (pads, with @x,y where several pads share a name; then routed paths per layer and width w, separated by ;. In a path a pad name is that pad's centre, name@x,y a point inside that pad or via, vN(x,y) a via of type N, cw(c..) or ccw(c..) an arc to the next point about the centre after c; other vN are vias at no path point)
FLTREFH: Q6.3 R41.1 R48.2 | length 288.5
  Top Layer w12: Q6.3@527.4,840 585,840 623.5,801.5 R48.2@623.5,695 R41.1@623.5,625
FLTREFL: R43.1 R45.2 U2.6 | length 418.5
  Top Layer w12: R43.1@840.56,626.3 R45.2@840.55,561.3 1043.7,561.3 1111.18,493.82 U2.6@1111.18,438.86
GND: C2.2 C3.2 C5.2 C6.2 C7.2 C8.2 C9.2 C10.2 C11.2 C12.2 C13.2 C14.2 C15.2 C18.2 C19.1 C20.1 C21.1 C22.1 C23.2 C25.1 C26.2 C27.2 C28.2 C29.1 C30.1 C31.1 C33.2 C34.2 C35.2 C36.2 C37.2 C38.2 C39.1 C40.2 C41.2 C42.2 C44.2 C46.2 D5.1 D6.2 D7.1 D8.2 J3.1 J4.3 l6.2 L7.1 Q5.2 R9.1 R10.1 R14.1 R15.2 R19.1 R27.1 R39.1 R45.1 R46.1 R47.1 R48.1 R49.1 TP2.1 U1.17 U1.21@1575,1120 U2.11 U2.12 U3.3 U4.4 | length 186.8
  Top Layer w15: v1(1320,1395) C27.2@1372,1395 ; U1.21@1536.61,1158.39 U1.17@1536.61,1236.14
  Top Layer w20: C3.2@463,1510 500,1510 v1(520,1510)
  other v1: 720,55 845,55 975,55 1115,55 1270,55 1439,55 1608,55 1777,60 1946,60 2115,60 2284,60 2453,60 2622,60 2791,60 2960,60 70,75 232.5,75 395,75 2355,105 865,125 1135,150 2650,175 2795,190 2105,195 975,200 1025,200 70,205 745,245 1000,245 2450,265 2450,310 2545,395 910,410 1495,420 710,440 235,445 1815,450 2105,455 830,480 2105,500 565,510 930,515 145,525 2975,525 65,535 1340,550 1975,600 450,605 2660,605 295,610 1605,610 915,620 2895,640 1970.01,644.1 65,675 380,690 935,710 745,715 870,720 1820,730 1380,735 1430,735 100,750 150,750 200,750 930,775 70,785 125,785 175,785 225,785 705,805 70,830 225,830 1320,840 70,875 225,875 2195,885 605,895 1210,935 265,1065 1740,1095 1345,1135 1205,1145 1940,1150 1740,1165 1050,1280 1090,1320 1050,1355 2360,1400 2705,1400 1050,1430 2710,1455 1080,1470 1675,1495 1050,1510 1530,1510 1820,1515 2675,1525 2090,1540 1045,1565 1295,1565 1600,1565 2985,1580 1075,1605 390,1610 1265,1610 1325,1610 1045,1645 1720,1675 2220,1675 2985,1742.5 1710,1745 2535,1765 1655,1775 1990,1830 680,1845 60,1905 2985,1905 2535,1927.5 705,1960 1720,1975 1785,1975 1875,1975 1935,1975 2025,1975 2085,1975 2175,1975 2235,1975 285,1995 250,2040 830,2060 60,2067.5 2985,2070 285,2075 630,2075 705,2075 775,2075 2535,2090 865,2095 1720,2095 1780,2095 1870,2095 1930,2095 2020,2095 2080,2095 2170,2095 2230,2095 60,2230 2985,2232.5 195,2270 320,2320 1835,2365 1990,2365 2115,2365 2280,2365 60,2375 2985,2395 375,2415 1910,2430 2200,2440 680,2445 60,2537.5 210,2560 373.24,2560 536.47,2560 699.71,2560 862.94,2560 1026.18,2560 1189.41,2560 1352.65,2560 1515.88,2560 1679.12,2560 1842.35,2560 2005.59,2560 2168.82,2560 2332.06,2560 2495.29,2560 2658.53,2560 2821.76,2560 2985,2560
  other v3: 1523.82,1076.69 1575,1076.69 1626.18,1076.69 1523.82,1120 1575,1120 1626.18,1120 1523.82,1163.31 1575,1163.31 1626.18,1163.31
  other v4: 1472.64,1076.69 1677.36,1076.69 1472.64,1120 1677.36,1120 1472.64,1163.31 1677.36,1163.31
IADJ: R13.1 R28.1 R40.2 | length 1400
  Top Layer w10: v1@1800,970 1828.5,941.5 R13.1@1863.5,941.5 ; R13.1@1865,940 R13.1@1863.5,941.5 ; R13.1@1865,941.5 R13.1@1863.5,941.5
  Top Layer w12: R28.1@1679.64,544.46 1680.18,545 v1@1765,545 ; v1(1940,290) R40.2@1993.5,290
  Bottom Layer w10: 1770,720 1786,736 1786,742.01 1800,756.01 v1(1800,975) 1940,835 1940,775
  Bottom Layer w12: v1@1770,547.97 v1(1770,550) 1770,717.57 ; v1(1940,290) 1940,776.93
ILIMREF: R44.1 R46.2 U2.8 | length 191.6
  Top Layer w12: U2.8@1136.77,671.14 1198.86,671.14 1215.51,654.49 R44.1@1215.51,613.54 R46.2@1215.51,548.54
LEDN: C16.1 C17.2 L7.2 R36.1 R37.1
LEDP: C16.2 C17.1 J2.3 L5.2
NetC1_1: C1.1 R1.1
NetC1_2: C1.2 C18.1 C19.2 C20.2 C21.2 C22.2 C23.1 D2.3 R2.1 R5.2 R11.2 | length 682.6
  Top Layer w10: R5.2@2097,1670 2097,1745 2142,1790 2210,1790 2225,1805 2225,1892 R11.2@2253,1920 2297.5,1964.5 2297.5,2072.5 2330,2105 2390,2105 2400,2115 R2.1@2400,2152.09
  other v2: 1470,2165 1530,2165 1470,2220 1530,2220 1470,2275 1530,2275
NetC4_1: C4.1 D1.3 D3.3 l4.1 | length 223.9
  Top Layer w20: C4.1@448,1010 v1@495,1010
  Bottom Layer w20: v1(500,1010) 565,1075 v1(650,1075)
NetC4_2: C4.2 J1.3 l6.1 | length 194.1
  Top Layer w20: 200,1015 205,1010 C4.2@392,1010
NetC9_1: C9.1 C10.1 C11.1 C12.1 C13.1 L1.2 L2.1 R4.2 | length 1301.1
  Top Layer w12: L1.2@490,1910 495,1905 495,1825 535,1785 890,1785 927.91,1747.09 927.91,1594.56 930,1592.47 930,1549.62 930,1002.09 R4.2@927.91,1000
NetC14_1: C14.1 C15.1 L5.1 Q1.5 Q1.6 Q1.7 Q1.8 Q1.9
  other v3: 2490.75,1525 2490.75,1565
NetC24_1: C24.1 R3.1
NetC24_2: C24.2 Q2.1 Q2.2 Q2.3 R6.2 R9.2 | length 236.6
  Top Layer w10: R6.2@1372,1470 1372,1622 1400,1650 R9.2@1445,1650
NetC25_2: C25.2 pad.1@1400,1040 R4.1 U1.1 | length 481.6
  Top Layer w10: R4.1@1040,1030 1055,1045 1230,1045 1270,1005 C25.2@1275,1005 1320,1005 1355,1040 pad.1@1400,1040 1440,1040 1459.84,1020.16 U1.1@1459.84,1003.86
NetC27_1: C27.1 pad.1@1480,1325 R6.1 U1.18 | length 268.2
  Top Layer w10: R6.1@1428,1470 C27.1@1428,1395 1460,1363 1460,1345 pad.1@1480,1325 1500,1305 1500,1280 1511.02,1268.98 U1.18@1511.02,1236.14
NetC28_1: C28.1 pad.1@1591.15,1325 R5.1 R10.2 U1.15 | length 1023.5
  Top Layer w10: U1.15@1587.8,1236.14 1587.8,1270.3 1591.15,1273.65 pad.1@1591.15,1325 1591.15,1354.65 C28.1@1625,1388.5 1590,1423.5 1590,1470 1594.3,1474.3 1594.3,1476.15 1601.33,1483.18 1603.18,1483.18 1616.99,1496.99 1616,1497.99 1616,1522.01 1632.99,1539 1657.01,1539 1658.01,1538.01 1785,1665 v1(1870,1665) ; v1(1975,1645) 2025,1645 2072,1598 R10.2@2150,1598 2150,1635 2153,1638 R5.1@2153,1670
  Bottom Layer w10: v1(1870,1665) 1955,1665 v1(1975,1645)
NetC30_2: C30.2 pad.1@1475,912.5 U1.3 U1.4 | length 217.4
  Top Layer w10: C30.2@1404.43,912.5 pad.1@1475,912.5 1491,928.5 1498.5,928.5 1536.61,966.61 U1.4@1536.61,1003.86
  Top Layer w12: U1.3@1511.02,1003.86 U1.4@1536.61,1003.86
NetC31_2: C31.2 pad.1@1530,910 U1.5 | length 246.1
  Top Layer w10: C31.2@1433,830 1465,830 1495,860 1495,875 pad.1@1530,910 1550,930 1550,955 1562.2,967.2 U1.5@1562.2,1003.86
NetC32_1: C32.1 C34.1 pad.1@1645,1320 R11.1 U1.14 | length 982.4
  Top Layer w10: U1.14@1613.39,1236.14 1613.39,1288.39 pad.1@1645,1320 1680,1355 1680,1420 1750,1490 C32.1@1750,1536.93 1761.93,1536.93 1838,1613 C34.1@1875,1613 1889.5,1627.5 1889.5,1637.5 2144,1892 2192,1892 2197,1897 R11.1@2197,1920
NetC32_2: C32.2 C33.1 pad.1@1705,1317.5 R12.1 U1.13 | length 1012.2
  Top Layer w10: U1.13@1638.98,1236.14 1638.98,1278.98 1648,1288 1658.25,1288 1670.25,1300 1687.5,1300 pad.1@1705,1317.5 1705,1370 1738.07,1403.07 C32.2@1750,1403.07 1813.07,1403.07 1823.5,1413.5 C33.1@1875,1413.5 1910,1448.5 1910,1632.5 2152.5,1875 2190,1875 2197,1868 R12.1@2197,1845
NetC35_1: C35.1 pad.1@1727.5,1237.5 U1.11 | length 116.2
  Top Layer w10: U1.11@1690.16,1236.14 1726.14,1236.14 pad.1@1727.5,1237.5 1757.5,1237.5 1771.5,1251.5 C35.1@1800,1251.5
NetC36_1: C36.1 pad.1@1725,950 R13.2 U1.9 | length 274.1
  Top Layer w10: U1.9@1669.3,999.13 U1.9@1664.57,1003.86 1664.57,970.43 1670.7,964.3 1702.84,964.3 1712.14,955 pad.1@1715,955 ; pad.1@1725,950 1775,950 1780,945 C36.1@1780,920 ; C36.1@1785,915 1828.5,915 R13.2@1865,878.5
NetC37_1: C37.1 pad.1@1677.5,930 U1.8 | length 169.2
  Top Layer w10: U1.8@1638.98,1003.86 1638.98,968.52 pad.1@1677.5,930 ; pad.1@1675,930 1705,900 C37.1@1705,863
